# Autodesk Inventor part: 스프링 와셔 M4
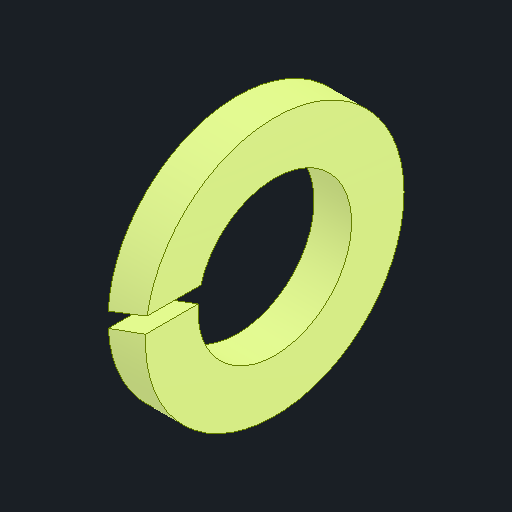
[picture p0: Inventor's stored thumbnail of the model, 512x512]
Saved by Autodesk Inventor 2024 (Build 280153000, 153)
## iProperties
Created: 2024-05
Part Number: 스프링 와셔 M4
Material: 강철, 연강
Description: 스프링 잠금 와셔
Document SubType Name: Modeling
Designer: kh_501
Density: 7.85 g/cm^3
Appearance: 기본값
Sending System: Autodesk Inventor 2025
Preprocessor: ST-DEVELOPER v20
Author: jhkim
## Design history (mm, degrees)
feature "Solid1"
node "솔리드1"
